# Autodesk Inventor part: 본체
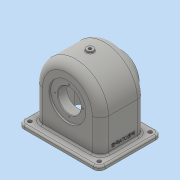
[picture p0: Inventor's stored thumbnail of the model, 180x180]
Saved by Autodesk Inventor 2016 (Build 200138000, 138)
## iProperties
Created: 2022-09
Part Number: 본체
Material: 일반
Document SubType Name: Modeling
Designer: PC-1-10
Density: 1 g/cm^3
Appearance: 기본값
Mass: 290.754 g
Surface Area: 1042.06 cm^2
Volume: 290.754 cm^3
Author: PC-1-10
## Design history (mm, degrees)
sketch "스케치1"
  geometry: L1 (54, 70)-(-54, 70); L2 (-54, 70)-(-54, -70); L3 (-54, -70)-(54, -70); L4 (54, -70)-(54, 70); L5 (-54, 70)-(54, -70); 2 further points
  constraints: 10 end point, 2 parallel, 1 coincident, 1 horizontal, 1 midpoint, 1 perpendicular
  dimensions: "d0" = 140 distance between parallel lines of L3 L1; "d1" = 108 distance between parallel lines of L2 L4
extrude "돌출1" new body sketch "스케치1" distance "d2" = 7; taper "d3" = 0 deg
sketch "스케치2"
  geometry: L1 (0, 57)-(0, -57); L2 (0, -57)-(64, -57); L3 (64, -57)-(64, 57); L4 (64, 57)-(0, 57); L5 (0, -70)-(0, 70) reference; A1 r 57 centre (64, 0) between (64, -57) and (64, 57); 1 further point
  constraints: 8 end point, 3 midpoint, 2 parallel, 2 point on circle, 1 centre point, 1 perpendicular, 1 vertical
  dimensions: "d4" = 57 radius of A1; "d5" = 64 distance between parallel lines of L3 L1
extrude "돌출2" join sketch "스케치2" stored distance "d6" = 78; taper "d7" = 0 deg
fillet "모깎기1" dims "d8" = 14
feature "쉘1" dims "d9" = 5
sketch "스케치3"
  geometry: L1 (15, -22)-(15, -108) reference; L2 (74, -13)-(24, -13) reference; L3 (83, -108)-(83, -22) reference; L4 (24, -117)-(74, -117) reference; L5 (0, 0)-(98, 0) reference; L6 (0, -130)-(0, 0) reference; L7 (98, -130)-(0, -130) reference; L8 (98, 0)-(98, -130) reference; A1 r 9 centre (24, -22) between (24, -13) and (15, -22) reference; A2 r 9 centre (74, -22) between (83, -22) and (74, -13) reference; A3 r 9 centre (74, -108) between (74, -117) and (83, -108) reference; A4 r 9 centre (24, -108) between (15, -108) and (24, -117) reference; 1 further point
extrude "돌출3" join sketch "스케치3" stored distance "d10" = 78; taper "d11" = 0 deg
node "작업 평면1"
sketch "스케치4"
  geometry: L1 (0, -70)-(0, 70) reference; C1 r 31 at (-64, 0); 2 further points
  constraints: 1 centre point, 1 horizontal alignment, 1 midpoint
  dimensions: "d13" = 62 diameter of C1; "d14" = 64 distance from line of C1.centre L1
extrude "돌출4" join sketch "스케치4" stored distance "d15" = 78; taper "d16" = 0 deg
node "작업 평면2"
sketch "스케치5"
  geometry: C1 r 6 at (0, 0); 1 further point
  constraints: 1 centre point, 1 coincident
  dimensions: "d18" = 12 diameter of C1
extrude "돌출5" join sketch "스케치5" stored distance "d19" = 78; taper "d20" = 0 deg
sketch "스케치6"
  geometry: C1 r 28 at (-43, 64); A1 r 43 centre (-43, 64) between (0, 64) and (-86, 64) reference; 1 further point
  constraints: 1 centre point, 1 concentric
  dimensions: "d21" = 56 diameter of C1
extrude "돌출6" join sketch "스케치6" distance "d22" = 14; taper "d23" = 0 deg
feature "면 기울기1" dims angle "d24" = 30 deg
hole "구멍1" diameter "d27" = 40; stored, may be unused: countersink angle "d31" = 90 deg, drill point angle "d33" = 118 deg; dims "d25" = 10, "d26" = 10, "d28" = 6, "d29" = 64, "d30" = 3, "d32" = 29
hole "구멍2" diameter "d36" = 35; stored, may be unused: countersink angle "d40" = 90 deg, drill point angle "d42" = 118 deg; dims "d34" = 10, "d35" = 10, "d37" = 6, "d38" = 40, "d39" = 16, "d41" = 20
hole "구멍3" diameter "d45" = 5.188; stored, may be unused: countersink angle "d49" = 90 deg, drill point angle "d51" = 118 deg; dims "d43" = 10, "d44" = 10, "d46" = 12, "d47" = 40, "d48" = 16, "d50" = 16
sketch "스케치7" dims "d52" = 48
  geometry: C1 r 31 at (0, 0) reference; 3 further points
  constraints: 1 vertical alignment, 3 other
hole "구멍4" sketch "스케치7" at (0, 24) diameter "d53" = 2.459; stored, may be unused: countersink angle "d57" = 90 deg, drill point angle "d59" = 118 deg; dims "d54" = 7, "d55" = 40, "d56" = 16, "d58" = 9
sketch "스케치8"
  geometry: C1 r 24 at (0, 0); C2 r 32 at (0, 0) reference; C3 r 1.23 at (0, 24) reference; 2 further points
  constraints: 1 centre point, 1 coincident, 1 concentric
  dimensions: "d63" = 48 diameter of C1
hole "구멍5" sketch "스케치8" at (0, 24) diameter "d64" = 2.459; stored, may be unused: countersink angle "d68" = 90 deg, drill point angle "d70" = 118 deg; dims "d65" = 7, "d66" = 40, "d67" = 16, "d69" = 9
fillet "모깎기2" dims "d74" = 10
fillet "모깎기3" dims "d75" = 3
fillet "모깎기4" dims "d76" = 1
fillet "모깎기5" dims "d77" = 3
hole "구멍6" diameter "d80" = 6.6; stored, may be unused: countersink angle "d84" = 90 deg, drill point angle "d86" = 118 deg; dims "d78" = 10, "d79" = 10, "d81" = 7, "d82" = 40, "d83" = 16, "d85" = 9
hole "구멍7" diameter "d89" = 6.6; stored, may be unused: countersink angle "d93" = 90 deg, drill point angle "d95" = 118 deg; dims "d87" = 10, "d88" = 10, "d90" = 7, "d91" = 40, "d92" = 16, "d94" = 9
hole "구멍8" diameter "d98" = 6.6; stored, may be unused: countersink angle "d102" = 90 deg, drill point angle "d104" = 118 deg; dims "d96" = 10, "d97" = 10, "d99" = 7, "d100" = 40, "d101" = 16, "d103" = 9
hole "구멍9" diameter "d107" = 6.6; stored, may be unused: countersink angle "d111" = 90 deg, drill point angle "d113" = 118 deg; dims "d105" = 10, "d106" = 10, "d108" = 7, "d109" = 40, "d110" = 16, "d112" = 9
fillet "모깎기6" dims "d114" = 3
fillet "모깎기7" dims "d115" = 3
fillet "모깎기8" dims "d116" = 0.6
chamfer "모따기1" distance "d117" = 1; stored, may be unused: second distance "d118" = 2, angle "d119" = 45 deg
fillet "모깎기9" dims "d120" = 3
node "작업 평면3"
sketch "스케치9"
  geometry: L1 (-25, 22)-(25, 22); L2 (25, 22)-(25, 12); L3 (25, 12)-(-25, 12); L4 (-25, 12)-(-25, 22); L5 (-25, 17)-(25, 17); L6 (0, 12)-(0, 22); L7 (-44, 0)-(44, 0) reference; L8 (-39, 64)-(-39, 10) reference; 1 further point
  constraints: 4 end point, 4 midpoint, 2 other
  dimensions: "d122" = 10 distance between parallel lines of L3 L1; "d123" = 50 distance between parallel lines of L2 L4; "d124" = 17 distance between parallel lines of L5 L7; "d125" = 39 distance between parallel lines of L6 L8
feature "엠보싱1" sketch "스케치9" dims "d126" = 0.5, "d127" = 0
node "솔리드1"
pattern_circular "원형 패턴1" dims angle "d61" = 360 deg
pattern_circular "원형 패턴2" dims angle "d72" = 360 deg
node "투영된 루프1"
other parameters: "d12" = -54, "d17" = 124, "d121" = -110.75
